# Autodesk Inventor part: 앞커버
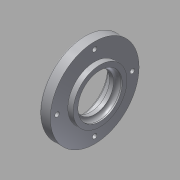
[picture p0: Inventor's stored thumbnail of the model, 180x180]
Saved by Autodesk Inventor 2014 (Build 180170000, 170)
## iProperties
Created: 2015-09
Part Number: 앞커버
Material: 알루미늄 6061
Document SubType Name: Modeling
Designer: mduedu
Density: 2.71 g/cm^3
Mass: 58.9874 g
Surface Area: 98.7754 cm^2
Volume: 21.7666 cm^3
Appearance: 알루미늄 - 평지
Author: mduedu
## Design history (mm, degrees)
sketch "스케치1"
  geometry: L1 (-8, 67)-(-12, 67); L2 (-12, 67)-(-12, 80); L3 (-12, 80)-(-20, 80); L4 (-20, 80)-(-20, 70.5); L5 (-23, 70.5)-(-23, 61); L6 (-23, 61)-(-8, 61); L7 (-8, 61)-(-8, 67); L8 (-79.5, 39.5)-(-79.5, 54.5) reference; L9 (48.5, 54.5)-(48.5, 39.5) reference; L10 (-79.5, 47)-(48.5, 47); L11 (-20, 70.5)-(-23, 70.5); 3 further points
  constraints: 18 end point, 6 parallel, 4 midpoint, 1 horizontal, 1 perpendicular, 1 vertical alignment
  dimensions: "d0" = 15 distance between parallel lines of L7 L5; "d2" = 28 diameter of L6 L10; "d3" = 40 diameter of L1 L10; "d5" = 4 distance of L1.start L1.end; "d6" = 66 diameter of L3 L10; "d7" = 8 distance of L2.end L3.end; "d8" = 47 diameter of L4.end L10
revolve "회전1" sketch "스케치1" stored, may be unused: angle "d4" = 90 deg
sketch "스케치2"
  geometry: C1 r 33 at (0, 0) reference; 2 further points
  constraints: 1 coincident
hole "구멍1" sketch "스케치2" at (0, 0) diameter "d11" = 33; stored, may be unused: countersink angle "d15" = 90 deg, drill point angle "d17" = 0 deg; dims "d12" = 6, "d13" = 4, "d14" = 2, "d16" = 4
fillet "모깎기1" dims "d18" = 3
fillet "모깎기2" dims "d19" = 1
sketch "스케치3"
  geometry: C1 r 33 at (0, 0) reference; 2 further points
  constraints: 1 coincident
hole "구멍2" sketch "스케치3" at (0, 0) diameter "d20" = 40; stored, may be unused: countersink angle "d24" = 90 deg, drill point angle "d26" = 0 deg; dims "d21" = 6, "d22" = 4, "d23" = 2, "d25" = 8
fillet "모깎기3" dims "d27" = 0.4
chamfer "모따기1" distance "d28" = 1; stored, may be unused: second distance "d29" = 2, angle "d30" = 30 deg
sketch "스케치4" dims "d31" = 56
  geometry: C1 r 33 at (0, 0) reference; 6 further points
  constraints: 2 vertical alignment, 1 coincident, 7 other
  dimensions: "d36" = 360 deg dimension on C1.centre point (0, 28) (derived)
sketch "스케치7"
  geometry: 4 further points
hole "구멍4" sketch "스케치7" at (0, 28), (-28, 0), (28, 0), (0, -28) diameter "d48" = 3.4; stored, may be unused: countersink angle "d52" = 90 deg, drill point angle "d54" = 0 deg; dims "d49" = 6, "d50" = 6.5, "d51" = 3.4, "d53" = 8
node "솔리드1"
node "참조1"
node "참조2"
